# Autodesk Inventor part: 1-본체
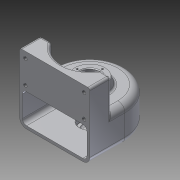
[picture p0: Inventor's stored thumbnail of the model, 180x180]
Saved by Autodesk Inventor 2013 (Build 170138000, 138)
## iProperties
Created: 2015-02
Part Number: 1-본체
Material: 알루미늄 6061
Document SubType Name: Modeling
Designer: Administrator
Density: 2.71 g/cm^3
Mass: 575.525 g
Surface Area: 706.561 cm^2
Volume: 212.371 cm^3
Author: Administrator
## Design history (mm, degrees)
sketch "스케치1"
  geometry: L1 (-50, 0)-(-50, -50); L2 (50, 0)-(50, -50); L3 (-50, -50)-(50, -50); A1 r 50 centre (0, 0) between (-50, 0) and (50, 0); 1 further point
  constraints: 6 end point, 2 point on circle, 2 tangent, 1 centre point, 1 coincident, 1 parallel, 1 perpendicular, 1 vertical
  dimensions: "d0" = 100 diameter of A1; "d6" = 50 distance from line of point (0, 0) L3
extrude "돌출1" new body sketch "스케치1" distance "d4" = 50; taper "d5" = 0 deg
node "작업 평면1"
sketch "스케치3"
  geometry: L1 (-50, 0)-(-50, -50) reference; L2 (-50, -50)-(50, -50) reference; L3 (50, -50)-(50, 0) reference; L4 (-50, -50)-(50, -50); L5 (50, -50)-(50, -20); L6 (-50, -20)-(-50, -50); L7 (50, -20)-(34.641, -20); L8 (-34.641, -20)-(-50, -20); A1 r 40 centre (0, 0) between (-34.641, -20) and (34.641, -20); 1 further point
  constraints: 10 end point, 3 parallel, 2 point on circle, 1 centre point, 1 coincident, 1 horizontal, 1 perpendicular, 1 point on line
  dimensions: "d8" = 30 distance of L6.start L1.end; "d9" = 80 diameter of A1; "d10" = 20 distance from line of point (0, 0) L7
extrude "돌출2" join sketch "스케치3" stored distance "d11" = 50; taper "d12" = 0 deg
sketch "스케치4"
  geometry: L1 (50, 50)-(0, 50) reference; L2 (0, 50)-(-20, 50) reference; L3 (25, 50)-(21.36, 60); L4 (0, 195.305)-(0, 0); L5 (25, 50)-(0, 50); L6 (21.36, 60)-(0, 60); L7 (0, 60)-(0, 50); 1 further point
  constraints: 10 end point, 2 collinear, 2 perpendicular, 1 coincident, 1 midpoint, 1 point on line
  dimensions: "d13" = 110 deg angle of L1 L3; "d14" = 50 diameter of L3.start L4; "d16" = 10 vertical distance of L1.end L3.end
revolve "회전1" sketch "스케치4" stored, may be unused: angle "d17" = 90 deg
node "작업 평면2"
sketch "스케치5"
  geometry: L1 (-50, -50)-(50, -50) reference; L2 (-46, 0)-(-46, -50); L3 (-46, -50)-(46, -50); L4 (46, 0)-(46, -50); A1 r 46 centre (0, 0) between (-46, 0) and (46, 0); 1 further point
  constraints: 6 end point, 2 perpendicular, 2 point on circle, 2 point on line, 2 tangent, 1 centre point, 1 coincident
  dimensions: "d19" = 92 diameter of A1
extrude "돌출3" cut sketch "스케치5" stored distance "d21" = 42; taper "d22" = 0 deg
fillet "모깎기1" dims "d23" = 6
sketch "스케치6"
  geometry: C1 r 21.36 at (0, 0) reference; 1 further point
  constraints: 1 coincident
hole "구멍1" sketch "스케치6" at (0, 0) diameter "d24" = 20; stored, may be unused: countersink angle "d28" = 90 deg, drill point angle "d30" = 0 deg; dims "d25" = 6, "d26" = 28, "d27" = 10, "d29" = 4
sketch "스케치7"
  geometry: C1 r 20 at (0, 0); A1 r 50 centre (0, 0) between (50, 0) and (-50, 0) reference
  constraints: 1 centre point, 1 coincident
  dimensions: "d31" = 40 diameter of C1
extrude "돌출4" join sketch "스케치7" distance "d33" = 9; taper "d34" = 0 deg
sketch "스케치8"
  geometry: C1 r 14 at (0, 0); A1 r 40 centre (0, 0) between (40, 0) and (-40, 0) reference; 1 further point
  constraints: 2 coincident, 1 centre point
  dimensions: "d35" = 28 diameter of C1
hole "구멍2" sketch "스케치8" at (0, 0) diameter "d37" = 20; stored, may be unused: countersink angle "d41" = 90 deg, drill point angle "d43" = 0 deg; dims "d38" = 6, "d39" = 28, "d40" = 8, "d42" = 2
fillet "모깎기2" dims "d44" = 3
fillet "모깎기3" dims "d45" = 0.3
chamfer "모따기1" distance "d46" = 1; stored, may be unused: second distance "d47" = 2, angle "d48" = 45 deg
fillet "모깎기4" dims "d49" = 3
fillet "모깎기5" dims "d50" = 10
fillet "모깎기8" dims "d53" = 3
sketch "스케치9"
  geometry: C1 r 14 at (0, 0) reference; 1 further point
  constraints: 1 vertical alignment
  dimensions: "d54" = 18 distance of C1.centre point (0, 18)
hole "구멍3" sketch "스케치9" at (0, 18) diameter "d55" = 2.459; stored, may be unused: countersink angle "d59" = 90 deg, drill point angle "d61" = 118 deg; dims "d56" = 6, "d57" = 4, "d58" = 2, "d60" = 9
sketch "스케치10"
  geometry: L1 (0, 0)-(100, 0) reference; 5 further points
  constraints: 2 horizontal alignment, 2 vertical alignment
  dimensions: "d66" = 83.5 distance of point (91.75, -9) point (8.25, -9); "d67" = 9 distance from line of point (91.75, -9) L1; "d68" = 33 distance of point (91.75, -42) point (91.75, -9); "d69" = 41.75 horizontal distance of point (50, -95) point (8.25, -9)
hole "구멍4" sketch "스케치10" at (8.25, -9), (91.75, -9), (91.75, -42), (8.25, -42) diameter "d70" = 5.134; stored, may be unused: countersink angle "d74" = 90 deg, drill point angle "d76" = 118 deg; dims "d71" = 10, "d72" = 4, "d73" = 2, "d75" = 13
fillet "모깎기9" dims "d77" = 3
chamfer "모따기2" distance "d78" = 1; stored, may be unused: second distance "d79" = 2, angle "d80" = 45 deg
node "작업 평면3"
sketch "스케치11"
  geometry: L1 (40, 0)-(-40, 0) reference; 2 further points
  constraints: 1 vertical alignment, 1 other
  dimensions: "d82" = 25 distance from line of point (0, 25) L1
feature "엠보싱1" sketch "스케치11" dims "d0" = 100, "d6" = 50, "d83" = 0.5, "d84" = 0
fillet "모깎기10" dims "d85" = 3
fillet "모깎기11" dims "d86" = 3
fillet "모깎기12" dims "d87" = 0.3
node "솔리드1"
pattern_circular "원형 패턴1" dims angle "d63" = 360 deg
other parameters: "d7" = 45, "d18" = 25
